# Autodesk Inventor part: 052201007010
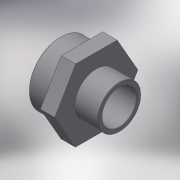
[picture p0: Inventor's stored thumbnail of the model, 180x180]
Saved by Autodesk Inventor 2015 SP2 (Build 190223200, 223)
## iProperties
Created: 2017-10
Part Number: 052201007010
Material: Generic
Description: PLASSON SOCKET NIPPLE THR. P 3/4"-1"
Document SubType Name: Modeling
Designer: KIM
Density: 1 g/cm^3
Appearance: Default
Author: KIM
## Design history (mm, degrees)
derived "052201.ipt"
feature "Solid1::052201.ipt"
tag "TaggingFeature1"
body "Solid1"
other parameters: "d0" = 45, "d2" = 46, "d13" = 0, "d14" = 0.30291, "d17" = 17, "d18" = 24, "d19" = 37.40939, "d20" = 30.291, "d21" = 26.441, "d22" = 13.6, "d23" = 28.77645, "d24" = 21.1528, "d26" = -17, "G_" = 30.291, "R_" = 26.441, "C_" = 46, "lt_1" = 17, "H_" = 45
